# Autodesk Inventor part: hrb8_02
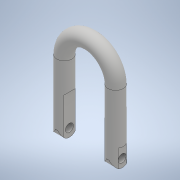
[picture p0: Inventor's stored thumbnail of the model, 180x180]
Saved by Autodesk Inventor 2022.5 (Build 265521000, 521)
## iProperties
Part Number: hrb8_02
Material: 一般
Document SubType Name: Modeling
Designer: ImaoCorp
Density: 1 g/cm^3
Appearance: 既定
Author: ImaoCorp
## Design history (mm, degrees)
feature "hrb8_02"
node "ソリッド1"
